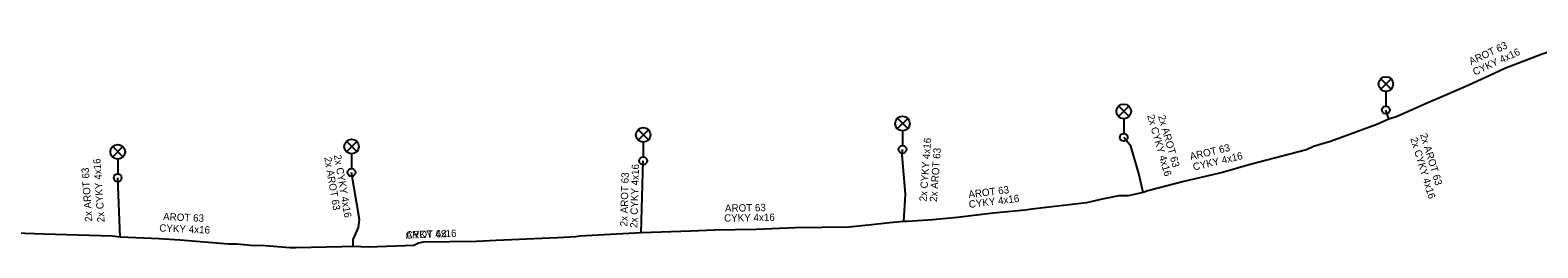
# Model space of a CAD drawing. Extents: x -641884 to -641258, y -1196509 to -1195931.
# Drawn here: x -641568.4 to -641414.3, y -1196059.4 to -1196037.2 of the extents above; entities that cross this region are included whole.
import ezdxf

# ---------------------------------------------------------------- set-up
doc = ezdxf.new("R2010")
doc.units = 0
for name, color, linetype in [('TECH_OCHR_PÁSMO_HRAN', 7, 'Continuous'), ('Vrstva 22', 7, 'Continuous'), ('Vrstva 31', 7, 'Continuous'), ('ZP_EON', 7, 'Continuous'), ('ZP_EON_POPIS', 7, 'Continuous')]:
    doc.layers.add(name, color=color, linetype=linetype)

msp = doc.modelspace()

# ---------------------------------------------------------------- linework, layer by layer
at = {"layer": 'TECH_OCHR_PÁSMO_HRAN'}
for p, q in [((-641429.58, -1196046.27), (-641429.87, -1196045.32)), ((-641505.97, -1196057.88), (-641505.77, -1196050.51)), ((-641559.21, -1196058.31), (-641559.48, -1196052.24))]:
    msp.add_line(p, q, dxfattribs=at)
for points in [[(-641407.1, -1196037.16), (-641411.04, -1196038.74), (-641413.9, -1196039.6), (-641417.7, -1196041.09), (-641418.86, -1196041.61), (-641421.39, -1196042.78), (-641423.73, -1196043.81), (-641425.57, -1196044.59), (-641428.73, -1196045.97), (-641429.58, -1196046.27)], [(-641429.58, -1196046.27), (-641430.79, -1196046.79), (-641435.54, -1196048.53), (-641437.27, -1196049.05), (-641437.99, -1196049.37), (-641443.75, -1196050.88), (-641446.55, -1196051.69), (-641449.48, -1196052.38), (-641450.53, -1196052.63), (-641454.18, -1196053.58), (-641454.68, -1196053.74)], [(-641454.68, -1196053.74), (-641455.13, -1196051.82), (-641455.94, -1196049.01), (-641456.66, -1196048.11)], [(-641479.15, -1196056.72), (-641478.98, -1196053.91), (-641479.31, -1196049.89), (-641479.27, -1196049.35)], [(-641535.4, -1196059.28), (-641535.42, -1196058.55), (-641534.88, -1196057.31), (-641534.76, -1196056.5), (-641535.58, -1196051.7)], [(-641454.68, -1196053.74), (-641456.19, -1196054.09), (-641457.15, -1196054.08), (-641458.88, -1196054.43), (-641460.45, -1196054.8), (-641466.04, -1196055.46), (-641466.74, -1196055.54), (-641469.99, -1196055.85), (-641473.65, -1196056.3), (-641476.19, -1196056.54), (-641478.76, -1196056.7), (-641479.15, -1196056.72)], [(-641559.21, -1196058.31), (-641560.06, -1196058.22), (-641567.01, -1196058.01), (-641572.92, -1196057.79), (-641576.36, -1196057.7), (-641577.6, -1196057.52), (-641578.14, -1196057.25), (-641578.63, -1196056.85), (-641580.93, -1196056.84), (-641582.91, -1196056.85), (-641586.46, -1196056.69), (-641590.66, -1196056.62), (-641593.07, -1196056.55), (-641593.52, -1196056.48), (-641593.96, -1196056.13), (-641594.25, -1196056), (-641594.6, -1196055.82), (-641595.26, -1196055.7)], [(-641505.97, -1196057.88), (-641512.24, -1196058.2), (-641512.66, -1196058.28), (-641514.58, -1196058.37), (-641520.79, -1196058.66), (-641522.81, -1196058.76), (-641528.25, -1196058.83), (-641528.74, -1196058.93), (-641529.23, -1196059.16), (-641533.86, -1196059.33), (-641535.4, -1196059.28)], [(-641479.15, -1196056.72), (-641480.56, -1196056.86), (-641482.75, -1196057.09), (-641484.77, -1196057.29), (-641490.23, -1196057.34), (-641494.23, -1196057.52), (-641498.49, -1196057.59), (-641500.9, -1196057.71), (-641505.97, -1196057.88)], [(-641535.4, -1196059.28), (-641536.57, -1196059.29), (-641541.26, -1196059.39), (-641541.84, -1196059.4), (-641544.85, -1196059.17), (-641545.5, -1196059.18), (-641547.31, -1196059.03), (-641548.17, -1196059.03), (-641553.11, -1196058.6), (-641555.24, -1196058.48), (-641559.21, -1196058.31)]]:
    msp.add_lwpolyline(points, dxfattribs=at)
at = {"layer": 'Vrstva 31'}
for p, q in [((-641430.4, -1196043.2), (-641429.34, -1196042.14)), ((-641429.33, -1196043.19), (-641430.38, -1196042.13)), ((-641429.87, -1196043.42), (-641429.87, -1196044.92)), ((-641457.19, -1196045.99), (-641456.13, -1196044.93)), ((-641456.12, -1196045.98), (-641457.17, -1196044.92)), ((-641506.3, -1196048.39), (-641505.24, -1196047.33)), ((-641505.23, -1196048.38), (-641506.28, -1196047.32)), ((-641479.8, -1196047.23), (-641478.74, -1196046.17)), ((-641478.73, -1196047.22), (-641479.78, -1196046.16)), ((-641456.66, -1196046.21), (-641456.66, -1196047.71)), ((-641536.11, -1196049.58), (-641535.05, -1196048.52)), ((-641535.04, -1196049.57), (-641536.09, -1196048.51)), ((-641505.77, -1196048.61), (-641505.77, -1196050.11)), ((-641479.27, -1196047.45), (-641479.27, -1196048.95)), ((-641560.01, -1196050.12), (-641558.95, -1196049.06)), ((-641558.94, -1196050.11), (-641559.99, -1196049.05)), ((-641559.48, -1196050.34), (-641559.48, -1196051.84)), ((-641535.58, -1196049.8), (-641535.58, -1196051.3))]:
    msp.add_line(p, q, dxfattribs=at)
for centre, radius in [((-641429.87, -1196042.67), 0.75), ((-641456.66, -1196045.46), 0.75), ((-641429.87, -1196045.32), 0.4), ((-641505.77, -1196047.86), 0.75), ((-641479.27, -1196046.7), 0.75), ((-641559.48, -1196049.59), 0.75), ((-641535.58, -1196049.05), 0.75), ((-641479.27, -1196049.35), 0.4), ((-641456.66, -1196048.11), 0.4), ((-641505.77, -1196050.51), 0.4), ((-641559.48, -1196052.24), 0.4), ((-641535.58, -1196051.7), 0.4)]:
    msp.add_circle(centre, radius, dxfattribs=at)
at = {"layer": 'ZP_EON'}
for p, q in [((-641429.58, -1196046.27), (-641429.87, -1196045.32)), ((-641505.97, -1196057.88), (-641505.77, -1196050.51)), ((-641559.21, -1196058.31), (-641559.48, -1196052.24))]:
    msp.add_line(p, q, dxfattribs=at)
for points in [[(-641407.1, -1196037.16), (-641411.04, -1196038.74), (-641413.9, -1196039.6), (-641417.7, -1196041.09), (-641418.86, -1196041.61), (-641421.39, -1196042.78), (-641423.73, -1196043.81), (-641425.57, -1196044.59), (-641428.73, -1196045.97), (-641429.58, -1196046.27)], [(-641429.58, -1196046.27), (-641430.79, -1196046.79), (-641435.54, -1196048.53), (-641437.27, -1196049.05), (-641437.99, -1196049.37), (-641443.75, -1196050.88), (-641446.55, -1196051.69), (-641449.48, -1196052.38), (-641450.53, -1196052.63), (-641454.18, -1196053.58), (-641454.68, -1196053.74)], [(-641454.68, -1196053.74), (-641455.13, -1196051.82), (-641455.94, -1196049.01), (-641456.66, -1196048.11)], [(-641479.15, -1196056.72), (-641478.98, -1196053.91), (-641479.31, -1196049.89), (-641479.27, -1196049.35)], [(-641535.4, -1196059.28), (-641535.42, -1196058.55), (-641534.88, -1196057.31), (-641534.76, -1196056.5), (-641535.58, -1196051.7)], [(-641454.68, -1196053.74), (-641456.19, -1196054.09), (-641457.15, -1196054.08), (-641458.88, -1196054.43), (-641460.45, -1196054.8), (-641466.04, -1196055.46), (-641466.74, -1196055.54), (-641469.99, -1196055.85), (-641473.65, -1196056.3), (-641476.19, -1196056.54), (-641478.76, -1196056.7), (-641479.15, -1196056.72)], [(-641559.21, -1196058.31), (-641560.06, -1196058.22), (-641567.01, -1196058.01), (-641572.92, -1196057.79), (-641576.36, -1196057.7), (-641577.6, -1196057.52), (-641578.14, -1196057.25), (-641578.63, -1196056.85), (-641580.93, -1196056.84), (-641582.91, -1196056.85), (-641586.46, -1196056.69), (-641590.66, -1196056.62), (-641593.07, -1196056.55), (-641593.52, -1196056.48), (-641593.96, -1196056.13), (-641594.25, -1196056), (-641594.6, -1196055.82), (-641595.26, -1196055.7)], [(-641505.97, -1196057.88), (-641512.24, -1196058.2), (-641512.66, -1196058.28), (-641514.58, -1196058.37), (-641520.79, -1196058.66), (-641522.81, -1196058.76), (-641528.25, -1196058.83), (-641528.74, -1196058.93), (-641529.23, -1196059.16), (-641533.86, -1196059.33), (-641535.4, -1196059.28)], [(-641479.15, -1196056.72), (-641480.56, -1196056.86), (-641482.75, -1196057.09), (-641484.77, -1196057.29), (-641490.23, -1196057.34), (-641494.23, -1196057.52), (-641498.49, -1196057.59), (-641500.9, -1196057.71), (-641505.97, -1196057.88)], [(-641535.4, -1196059.28), (-641536.57, -1196059.29), (-641541.26, -1196059.39), (-641541.84, -1196059.4), (-641544.85, -1196059.17), (-641545.5, -1196059.18), (-641547.31, -1196059.03), (-641548.17, -1196059.03), (-641553.11, -1196058.6), (-641555.24, -1196058.48), (-641559.21, -1196058.31)]]:
    msp.add_lwpolyline(points, dxfattribs=at)

# ---------------------------------------------------------------- texts
at = {"layer": 'Vrstva 22'}
for s, rotation, p in [('AROT 63', 24.8182, (-641421.16, -1196040.73)), ('2x AROT 63', 286.08, (-641453.16, -1196045.95)), ('AROT 63', 13.2514, (-641449.81, -1196050.45)), ('2x AROT 63', 286.9755, (-641426.39, -1196047.82)), ('2x AROT 63', 279.6944, (-641538.37, -1196050.18)), ('2x AROT 63', 85.7636, (-641475.75, -1196054.72)), ('2x AROT 63', 93.9029, (-641562.07, -1196056.69)), ('2x AROT 63', 88.4455, (-641507.39, -1196057.22)), ('AROT 63', 7.0094, (-641472.49, -1196054.32)), ('AROT 63', 0.9414, (-641497.41, -1196055.72)), ('AROT 63', 357.548, (-641554.85, -1196056.57)), ('AROT 63', 2.1028, (-641530.02, -1196058.46))]:
    msp.add_text(s, height=0.75, rotation=rotation, dxfattribs=at).set_placement(p)
at = {"layer": 'ZP_EON_POPIS'}
for s, rotation, p in [('CYKY 4x16', 24.8182, (-641420.78, -1196041.81)), ('2x CYKY 4x16', 286.08, (-641454.27, -1196045.89)), ('2x CYKY 4x16', 85.7636, (-641476.81, -1196054.69)), ('2x CYKY 4x16', 286.9755, (-641427.38, -1196048.23)), ('2x CYKY 4x16', 93.9029, (-641560.81, -1196056.76)), ('2x CYKY 4x16', 279.6944, (-641537.39, -1196049.94)), ('CYKY 4x16', 13.2514, (-641449.49, -1196051.51)), ('2x CYKY 4x16', 88.4455, (-641506.37, -1196057.37)), ('CYKY 4x16', 7.0094, (-641472.45, -1196055.33)), ('CYKY 4x16', 0.9414, (-641497.5, -1196056.73)), ('CYKY 4x16', 357.548, (-641555.24, -1196057.73)), ('CYKY 4x16', 2.1028, (-641530.02, -1196058.46))]:
    msp.add_text(s, height=0.75, rotation=rotation, dxfattribs=at).set_placement(p)

doc.saveas('drawing.dxf')
